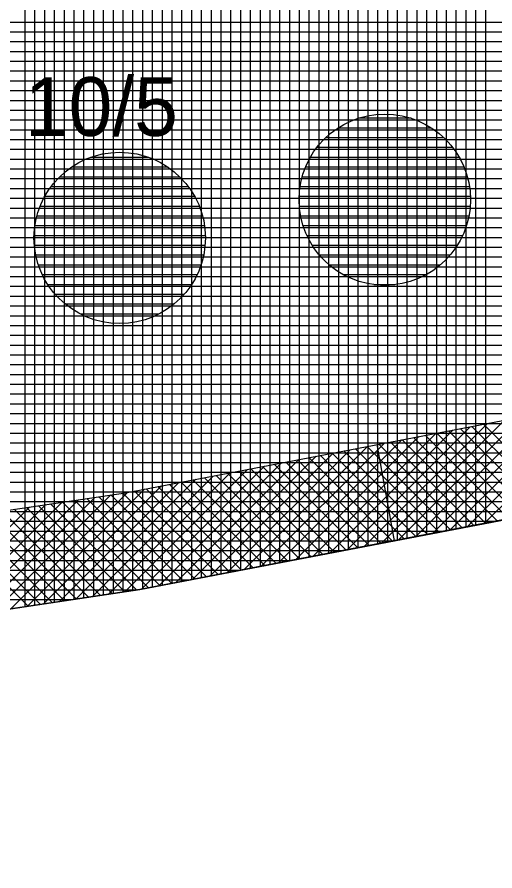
# Model space of a CAD drawing. Extents: x -565346 to -564154, y -1097386 to -1095620.
# Drawn here: x -564880.03 to -564870.28, y -1095808.72 to -1095791.27 of the extents above; entities that cross this region are included whole.
import ezdxf

# ---------------------------------------------------------------- set-up
doc = ezdxf.new("R2010")
doc.units = 0
for name, color, linetype in [('Vrstva 1', 7, 'Continuous'), ('Vrstva 40', 7, 'Continuous'), ('Vrstva 41', 7, 'Continuous'), ('Vrstva 42', 7, 'Continuous'), ('Vrstva 43', 7, 'Continuous'), ('Vrstva 44', 7, 'Continuous')]:
    doc.layers.add(name, color=color, linetype=linetype)

msp = doc.modelspace()

# ---------------------------------------------------------------- linework, layer by layer
at = {"layer": 'Vrstva 1'}
for p, q in [((-564877.52, -1095802.97), (-564694, -1095767.75)), ((-565025.24, -1095824.91), (-564877.52, -1095802.97))]:
    msp.add_line(p, q, dxfattribs=at)
at = {"layer": 'Vrstva 41'}
for p, q in [((-564870.842, -1095801.686), (-564868.327, -1095799.171)), ((-564870.491, -1095801.618), (-564867.977, -1095799.104)), ((-564871.542, -1095801.82), (-564869.027, -1095799.306)), ((-564871.192, -1095801.753), (-564868.677, -1095799.238)), ((-564872.592, -1095802.022), (-564870.077, -1095799.507)), ((-564872.242, -1095801.955), (-564869.727, -1095799.44)), ((-564871.892, -1095801.888), (-564869.377, -1095799.373)), ((-564873.643, -1095802.224), (-564871.127, -1095799.709)), ((-564873.293, -1095802.157), (-564870.777, -1095799.641)), ((-564872.943, -1095802.09), (-564870.427, -1095799.574)), ((-564869.281, -1095801.385), (-564870.985, -1095799.681)), ((-564869.044, -1095801.34), (-564870.748, -1095799.636)), ((-564868.806, -1095801.294), (-564870.51, -1095799.59)), ((-564874.343, -1095802.359), (-564871.827, -1095799.843)), ((-564873.993, -1095802.292), (-564871.477, -1095799.776)), ((-564870.23, -1095801.568), (-564871.934, -1095799.864)), ((-564869.993, -1095801.522), (-564871.697, -1095799.818)), ((-564869.755, -1095801.477), (-564871.46, -1095799.772)), ((-564869.518, -1095801.431), (-564871.222, -1095799.727)), ((-564875.394, -1095802.561), (-564872.877, -1095800.045)), ((-564875.044, -1095802.494), (-564872.527, -1095799.977)), ((-564874.694, -1095802.426), (-564872.177, -1095799.91)), ((-564871.179, -1095801.75), (-564872.883, -1095800.046)), ((-564872.328, -1095801.974), (-564872.68, -1095800.007)), ((-564870.941, -1095801.705), (-564872.646, -1095800)), ((-564870.704, -1095801.659), (-564872.409, -1095799.955)), ((-564870.467, -1095801.614), (-564872.171, -1095799.909)), ((-564876.094, -1095802.696), (-564873.577, -1095800.179)), ((-564875.744, -1095802.628), (-564873.227, -1095800.112)), ((-564872.128, -1095801.933), (-564873.833, -1095800.228)), ((-564871.89, -1095801.887), (-564873.595, -1095800.182)), ((-564871.653, -1095801.842), (-564873.358, -1095800.137)), ((-564871.416, -1095801.796), (-564873.121, -1095800.091)), ((-564877.145, -1095802.898), (-564874.628, -1095800.38)), ((-564876.795, -1095802.831), (-564874.278, -1095800.313)), ((-564876.445, -1095802.763), (-564873.927, -1095800.246)), ((-564873.076, -1095802.115), (-564874.782, -1095800.41)), ((-564872.839, -1095802.07), (-564874.544, -1095800.364)), ((-564872.602, -1095802.024), (-564874.307, -1095800.319)), ((-564872.365, -1095801.979), (-564874.07, -1095800.273)), ((-564878.162, -1095803.066), (-564875.678, -1095800.582)), ((-564877.829, -1095803.016), (-564875.328, -1095800.515)), ((-564877.495, -1095802.965), (-564874.978, -1095800.448)), ((-564874.025, -1095802.298), (-564875.731, -1095800.592)), ((-564873.788, -1095802.252), (-564875.494, -1095800.547)), ((-564873.551, -1095802.207), (-564875.256, -1095800.501)), ((-564873.314, -1095802.161), (-564875.019, -1095800.456)), ((-564878.828, -1095803.166), (-564876.378, -1095800.716)), ((-564878.495, -1095803.116), (-564876.028, -1095800.649)), ((-564874.737, -1095802.435), (-564876.443, -1095800.729)), ((-564874.5, -1095802.389), (-564876.206, -1095800.683)), ((-564874.262, -1095802.344), (-564875.968, -1095800.638)), ((-564879.826, -1095803.316), (-564877.428, -1095800.918)), ((-564879.493, -1095803.266), (-564877.078, -1095800.851)), ((-564879.16, -1095803.216), (-564876.728, -1095800.784)), ((-564875.686, -1095802.617), (-564877.392, -1095800.911)), ((-564875.449, -1095802.572), (-564877.155, -1095800.865)), ((-564875.211, -1095802.526), (-564876.917, -1095800.82)), ((-564874.974, -1095802.48), (-564876.68, -1095800.774)), ((-564880.825, -1095803.466), (-564878.444, -1095801.086)), ((-564880.492, -1095803.416), (-564878.112, -1095801.036)), ((-564880.159, -1095803.366), (-564877.778, -1095800.985)), ((-564876.872, -1095802.845), (-564878.607, -1095801.11)), ((-564876.635, -1095802.8), (-564878.361, -1095801.073)), ((-564876.397, -1095802.754), (-564878.115, -1095801.037)), ((-564876.16, -1095802.708), (-564877.869, -1095801)), ((-564875.923, -1095802.663), (-564877.629, -1095800.957)), ((-564882.156, -1095803.666), (-564879.773, -1095801.283)), ((-564881.823, -1095803.616), (-564879.44, -1095801.234)), ((-564881.49, -1095803.566), (-564879.108, -1095801.184)), ((-564881.157, -1095803.516), (-564878.776, -1095801.135)), ((-564877.832, -1095803.017), (-564879.592, -1095801.256)), ((-564877.586, -1095802.98), (-564879.346, -1095801.22)), ((-564877.346, -1095802.937), (-564879.1, -1095801.183)), ((-564877.109, -1095802.891), (-564878.854, -1095801.146)), ((-564879.061, -1095803.201), (-564880.824, -1095801.439)), ((-564878.815, -1095803.165), (-564880.578, -1095801.402)), ((-564878.57, -1095803.128), (-564880.331, -1095801.366)), ((-564878.324, -1095803.091), (-564880.085, -1095801.329)), ((-564878.078, -1095803.054), (-564879.839, -1095801.293)), ((-564879.799, -1095803.312), (-564881.563, -1095801.549)), ((-564879.553, -1095803.275), (-564881.316, -1095801.512)), ((-564879.307, -1095803.238), (-564881.07, -1095801.476))]:
    msp.add_line(p, q, dxfattribs=at)
at = {"layer": 'Vrstva 42'}
msp.add_lwpolyline([(-564912.15, -1095808.17), (-564912.447, -1095806.136), (-564877.814, -1095800.992), (-564725.004, -1095771.664), (-564724.6, -1095773.56), (-564877.52, -1095802.97)], close=True, dxfattribs=at)
at = {"layer": 'Vrstva 43'}
for p, q in [((-564871.27, -1095786.623), (-564871.27, -1095801.771)), ((-564871.07, -1095786.587), (-564871.07, -1095801.732)), ((-564870.87, -1095786.552), (-564870.87, -1095801.694)), ((-564870.67, -1095786.516), (-564870.67, -1095801.655)), ((-564870.47, -1095786.48), (-564870.47, -1095801.617)), ((-564872.27, -1095786.802), (-564872.27, -1095801.962)), ((-564872.07, -1095786.766), (-564872.07, -1095801.924)), ((-564871.87, -1095786.73), (-564871.87, -1095801.886)), ((-564871.67, -1095786.695), (-564871.67, -1095801.847)), ((-564871.47, -1095786.659), (-564871.47, -1095801.809)), ((-564873.27, -1095786.981), (-564873.27, -1095802.154)), ((-564873.07, -1095786.945), (-564873.07, -1095802.116)), ((-564872.87, -1095786.909), (-564872.87, -1095802.078)), ((-564872.67, -1095786.873), (-564872.67, -1095802.039)), ((-564872.47, -1095786.838), (-564872.47, -1095802.001)), ((-564874.27, -1095787.159), (-564874.27, -1095802.346)), ((-564874.07, -1095787.124), (-564874.07, -1095802.308)), ((-564873.87, -1095787.088), (-564873.87, -1095802.27)), ((-564873.67, -1095787.052), (-564873.67, -1095802.231)), ((-564873.47, -1095787.016), (-564873.47, -1095802.193)), ((-564875.07, -1095787.303), (-564875.07, -1095802.5)), ((-564874.87, -1095787.267), (-564874.87, -1095802.461)), ((-564874.67, -1095787.231), (-564874.67, -1095802.423)), ((-564874.47, -1095787.195), (-564874.47, -1095802.385)), ((-564876.07, -1095787.481), (-564876.07, -1095802.692)), ((-564875.87, -1095787.446), (-564875.87, -1095802.653)), ((-564875.67, -1095787.41), (-564875.67, -1095802.615)), ((-564875.47, -1095787.374), (-564875.47, -1095802.577)), ((-564875.27, -1095787.338), (-564875.27, -1095802.538)), ((-564877.07, -1095787.66), (-564877.07, -1095802.884)), ((-564876.87, -1095787.624), (-564876.87, -1095802.845)), ((-564876.67, -1095787.589), (-564876.67, -1095802.807)), ((-564876.47, -1095787.553), (-564876.47, -1095802.768)), ((-564876.27, -1095787.517), (-564876.27, -1095802.73)), ((-564878.07, -1095787.839), (-564878.07, -1095803.052)), ((-564877.87, -1095787.803), (-564877.87, -1095803.022)), ((-564877.67, -1095787.767), (-564877.67, -1095802.992)), ((-564877.47, -1095787.732), (-564877.47, -1095802.96)), ((-564877.27, -1095787.696), (-564877.27, -1095802.922)), ((-564879.07, -1095788.018), (-564879.07, -1095803.2)), ((-564878.87, -1095787.982), (-564878.87, -1095803.171)), ((-564878.67, -1095787.946), (-564878.67, -1095803.141)), ((-564878.47, -1095787.91), (-564878.47, -1095803.111)), ((-564878.27, -1095787.875), (-564878.27, -1095803.081)), ((-564879.87, -1095788.159), (-564879.87, -1095803.319)), ((-564879.67, -1095788.125), (-564879.67, -1095803.289)), ((-564879.47, -1095788.089), (-564879.47, -1095803.26)), ((-564879.27, -1095788.053), (-564879.27, -1095803.23)), ((-564817.128, -1095791.38), (-564901.56, -1095791.38)), ((-564818.17, -1095791.58), (-564902.907, -1095791.58)), ((-564819.213, -1095791.78), (-564904.254, -1095791.78)), ((-564820.255, -1095791.98), (-564905.601, -1095791.98)), ((-564821.297, -1095792.18), (-564906.947, -1095792.18)), ((-564822.339, -1095792.38), (-564908.294, -1095792.38)), ((-564823.381, -1095792.58), (-564909.641, -1095792.58)), ((-564824.423, -1095792.78), (-564910.988, -1095792.78)), ((-564825.465, -1095792.98), (-564912.335, -1095792.98)), ((-564826.507, -1095793.18), (-564913.681, -1095793.18)), ((-564827.55, -1095793.38), (-564915.028, -1095793.38)), ((-564828.592, -1095793.58), (-564916.375, -1095793.58)), ((-564829.634, -1095793.78), (-564917.722, -1095793.78)), ((-564830.676, -1095793.98), (-564919.068, -1095793.98)), ((-564831.718, -1095794.18), (-564920.415, -1095794.18)), ((-564832.76, -1095794.38), (-564921.762, -1095794.38)), ((-564833.802, -1095794.58), (-564923.109, -1095794.58)), ((-564834.845, -1095794.78), (-564924.456, -1095794.78)), ((-564835.887, -1095794.98), (-564925.802, -1095794.98)), ((-564836.929, -1095795.18), (-564927.149, -1095795.18)), ((-564837.971, -1095795.38), (-564928.496, -1095795.38)), ((-564839.013, -1095795.58), (-564929.843, -1095795.58)), ((-564840.055, -1095795.78), (-564931.189, -1095795.78)), ((-564841.097, -1095795.98), (-564932.536, -1095795.98)), ((-564842.14, -1095796.18), (-564933.883, -1095796.18)), ((-564843.182, -1095796.38), (-564935.23, -1095796.38)), ((-564844.224, -1095796.58), (-564936.577, -1095796.58)), ((-564845.266, -1095796.78), (-564937.923, -1095796.78)), ((-564846.308, -1095796.98), (-564939.27, -1095796.98)), ((-564847.35, -1095797.18), (-564940.617, -1095797.18)), ((-564848.392, -1095797.38), (-564941.964, -1095797.38)), ((-564849.434, -1095797.58), (-564943.31, -1095797.58)), ((-564850.477, -1095797.78), (-564944.657, -1095797.78)), ((-564851.519, -1095797.98), (-564946.004, -1095797.98)), ((-564852.561, -1095798.18), (-564947.351, -1095798.18)), ((-564853.603, -1095798.38), (-564948.697, -1095798.38)), ((-564854.645, -1095798.58), (-564950.044, -1095798.58)), ((-564855.687, -1095798.78), (-564951.391, -1095798.78)), ((-564856.729, -1095798.98), (-564952.738, -1095798.98)), ((-564857.772, -1095799.18), (-564954.085, -1095799.18)), ((-564858.814, -1095799.38), (-564955.431, -1095799.38)), ((-564859.856, -1095799.58), (-564956.778, -1095799.58)), ((-564860.898, -1095799.78), (-564958.125, -1095799.78)), ((-564861.94, -1095799.98), (-564959.472, -1095799.98)), ((-564862.982, -1095800.18), (-564960.818, -1095800.18)), ((-564864.024, -1095800.38), (-564962.165, -1095800.38)), ((-564865.066, -1095800.58), (-564963.512, -1095800.58)), ((-564866.109, -1095800.78), (-564964.859, -1095800.78)), ((-564867.151, -1095800.98), (-564966.206, -1095800.98)), ((-564868.193, -1095801.18), (-564967.552, -1095801.18)), ((-564869.235, -1095801.38), (-564968.899, -1095801.38)), ((-564870.277, -1095801.58), (-564970.246, -1095801.58)), ((-564871.319, -1095801.78), (-564971.593, -1095801.78)), ((-564872.361, -1095801.98), (-564972.939, -1095801.98)), ((-564873.404, -1095802.18), (-564974.286, -1095802.18)), ((-564874.446, -1095802.38), (-564975.633, -1095802.38)), ((-564875.488, -1095802.58), (-564976.98, -1095802.58)), ((-564876.53, -1095802.78), (-564978.326, -1095802.78)), ((-564877.587, -1095802.98), (-564979.673, -1095802.98)), ((-564878.934, -1095803.18), (-564981.02, -1095803.18))]:
    msp.add_line(p, q, dxfattribs=at)
msp.add_lwpolyline([(-564584.17, -1095730.99), (-564361.01, -1095672.63), (-564329.81, -1095662.26), (-564326.21, -1095642.73), (-564394.52, -1095662.95), (-564454.33, -1095677.56), (-564516.6, -1095690.89), (-564574.04, -1095705.03), (-564590.74, -1095715.12), (-564631.48, -1095731.18), (-564693.31, -1095752.31), (-564772.2, -1095768.91), (-564879.81, -1095788.15), (-565039.47, -1095811.86), (-565040.85, -1095849.94), (-565025.81, -1095848.33), (-565025.24, -1095824.91), (-564877.52, -1095802.97), (-564694, -1095767.75), (-564603.8, -1095739.23), (-564594.74, -1095734.52)], close=True, dxfattribs=at)
at = {"layer": 'Vrstva 44'}
for p, q in [((-564872.67, -1095793.26), (-564872.67, -1095796.746)), ((-564872.47, -1095793.256), (-564872.47, -1095796.751)), ((-564873.27, -1095793.423), (-564873.27, -1095796.585)), ((-564873.07, -1095793.343), (-564873.07, -1095796.665)), ((-564871.985, -1095793.34), (-564873.06, -1095793.34)), ((-564872.87, -1095793.29), (-564872.87, -1095796.718)), ((-564872.27, -1095793.274), (-564872.27, -1095796.734)), ((-564872.07, -1095793.316), (-564872.07, -1095796.694)), ((-564871.87, -1095793.382), (-564871.87, -1095796.625)), ((-564871.567, -1095793.54), (-564873.481, -1095793.54)), ((-564873.47, -1095793.533), (-564873.47, -1095796.476)), ((-564871.67, -1095793.478), (-564871.67, -1095796.529)), ((-564871.47, -1095793.61), (-564871.47, -1095796.4)), ((-564871.316, -1095793.74), (-564873.733, -1095793.74)), ((-564873.67, -1095793.684), (-564873.67, -1095796.324)), ((-564871.27, -1095793.785), (-564871.27, -1095796.222)), ((-564871.137, -1095793.94), (-564873.912, -1095793.94)), ((-564873.87, -1095793.888), (-564873.87, -1095796.121)), ((-564878.47, -1095794.12), (-564878.47, -1095797.448)), ((-564878.27, -1095794.068), (-564878.27, -1095797.5)), ((-564878.07, -1095794.04), (-564878.07, -1095797.527)), ((-564877.87, -1095794.037), (-564877.87, -1095797.531)), ((-564877.67, -1095794.056), (-564877.67, -1095797.513)), ((-564877.47, -1095794.099), (-564877.47, -1095797.471)), ((-564871.07, -1095794.032), (-564871.07, -1095795.974)), ((-564878.87, -1095794.306), (-564878.87, -1095797.262)), ((-564878.67, -1095794.198), (-564878.67, -1095797.37)), ((-564877.34, -1095794.14), (-564878.53, -1095794.14)), ((-564877.27, -1095794.166), (-564877.27, -1095797.401)), ((-564877.07, -1095794.264), (-564877.07, -1095797.304)), ((-564874.07, -1095794.188), (-564874.07, -1095795.82)), ((-564871.003, -1095794.14), (-564874.045, -1095794.14)), ((-564879.07, -1095794.455), (-564879.07, -1095797.113)), ((-564876.947, -1095794.34), (-564878.919, -1095794.34)), ((-564876.87, -1095794.397), (-564876.87, -1095797.172)), ((-564870.906, -1095794.34), (-564874.141, -1095794.34)), ((-564870.87, -1095794.436), (-564870.87, -1095795.57)), ((-564879.27, -1095794.656), (-564879.27, -1095796.914)), ((-564876.703, -1095794.54), (-564879.163, -1095794.54)), ((-564876.67, -1095794.576), (-564876.67, -1095796.992)), ((-564870.839, -1095794.54), (-564874.21, -1095794.54)), ((-564876.532, -1095794.74), (-564879.338, -1095794.74)), ((-564876.47, -1095794.828), (-564876.47, -1095796.739)), ((-564870.796, -1095794.74), (-564874.254, -1095794.74)), ((-564879.47, -1095794.949), (-564879.47, -1095796.62)), ((-564876.401, -1095794.94), (-564879.465, -1095794.94)), ((-564870.776, -1095794.94), (-564874.272, -1095794.94)), ((-564874.27, -1095794.893), (-564874.27, -1095795.106)), ((-564876.309, -1095795.14), (-564879.559, -1095795.14)), ((-564870.78, -1095795.14), (-564874.267, -1095795.14)), ((-564876.243, -1095795.34), (-564879.626, -1095795.34)), ((-564876.27, -1095795.243), (-564876.27, -1095796.319)), ((-564870.808, -1095795.34), (-564874.24, -1095795.34)), ((-564879.67, -1095795.576), (-564879.67, -1095795.999)), ((-564876.202, -1095795.54), (-564879.666, -1095795.54)), ((-564870.86, -1095795.54), (-564874.189, -1095795.54)), ((-564876.185, -1095795.74), (-564879.682, -1095795.74)), ((-564870.938, -1095795.74), (-564874.111, -1095795.74)), ((-564876.192, -1095795.94), (-564879.675, -1095795.94)), ((-564871.047, -1095795.94), (-564874, -1095795.94)), ((-564876.223, -1095796.14), (-564879.646, -1095796.14)), ((-564871.195, -1095796.14), (-564873.855, -1095796.14)), ((-564876.277, -1095796.34), (-564879.593, -1095796.34)), ((-564871.397, -1095796.34), (-564873.652, -1095796.34)), ((-564876.356, -1095796.54), (-564879.511, -1095796.54)), ((-564871.69, -1095796.54), (-564873.36, -1095796.54)), ((-564876.47, -1095796.74), (-564879.398, -1095796.74)), ((-564872.32, -1095796.74), (-564872.744, -1095796.74)), ((-564876.622, -1095796.94), (-564879.247, -1095796.94)), ((-564876.831, -1095797.14), (-564879.039, -1095797.14)), ((-564877.137, -1095797.34), (-564878.735, -1095797.34))]:
    msp.add_line(p, q, dxfattribs=at)
for centre in [(-564872.524, -1095795.004), (-564877.934, -1095795.784)]:
    msp.add_circle(centre, 1.75, dxfattribs=at)

# ---------------------------------------------------------------- texts
at = {"layer": 'Vrstva 40'}
msp.add_text('10/5', height=1.2, dxfattribs=at).set_placement((-564879.87, -1095793.7))

doc.saveas('drawing.dxf')
